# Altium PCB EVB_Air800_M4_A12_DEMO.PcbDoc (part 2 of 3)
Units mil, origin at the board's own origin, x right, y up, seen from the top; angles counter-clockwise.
Board outline 2106 x 2583.39 mil, 2 copper layers (Top, Bottom), stack 12.7 mil thick; 125 components, 94 nets, 414 pads, 454 vias.
Unrouted connection lines stored in the file: 290.
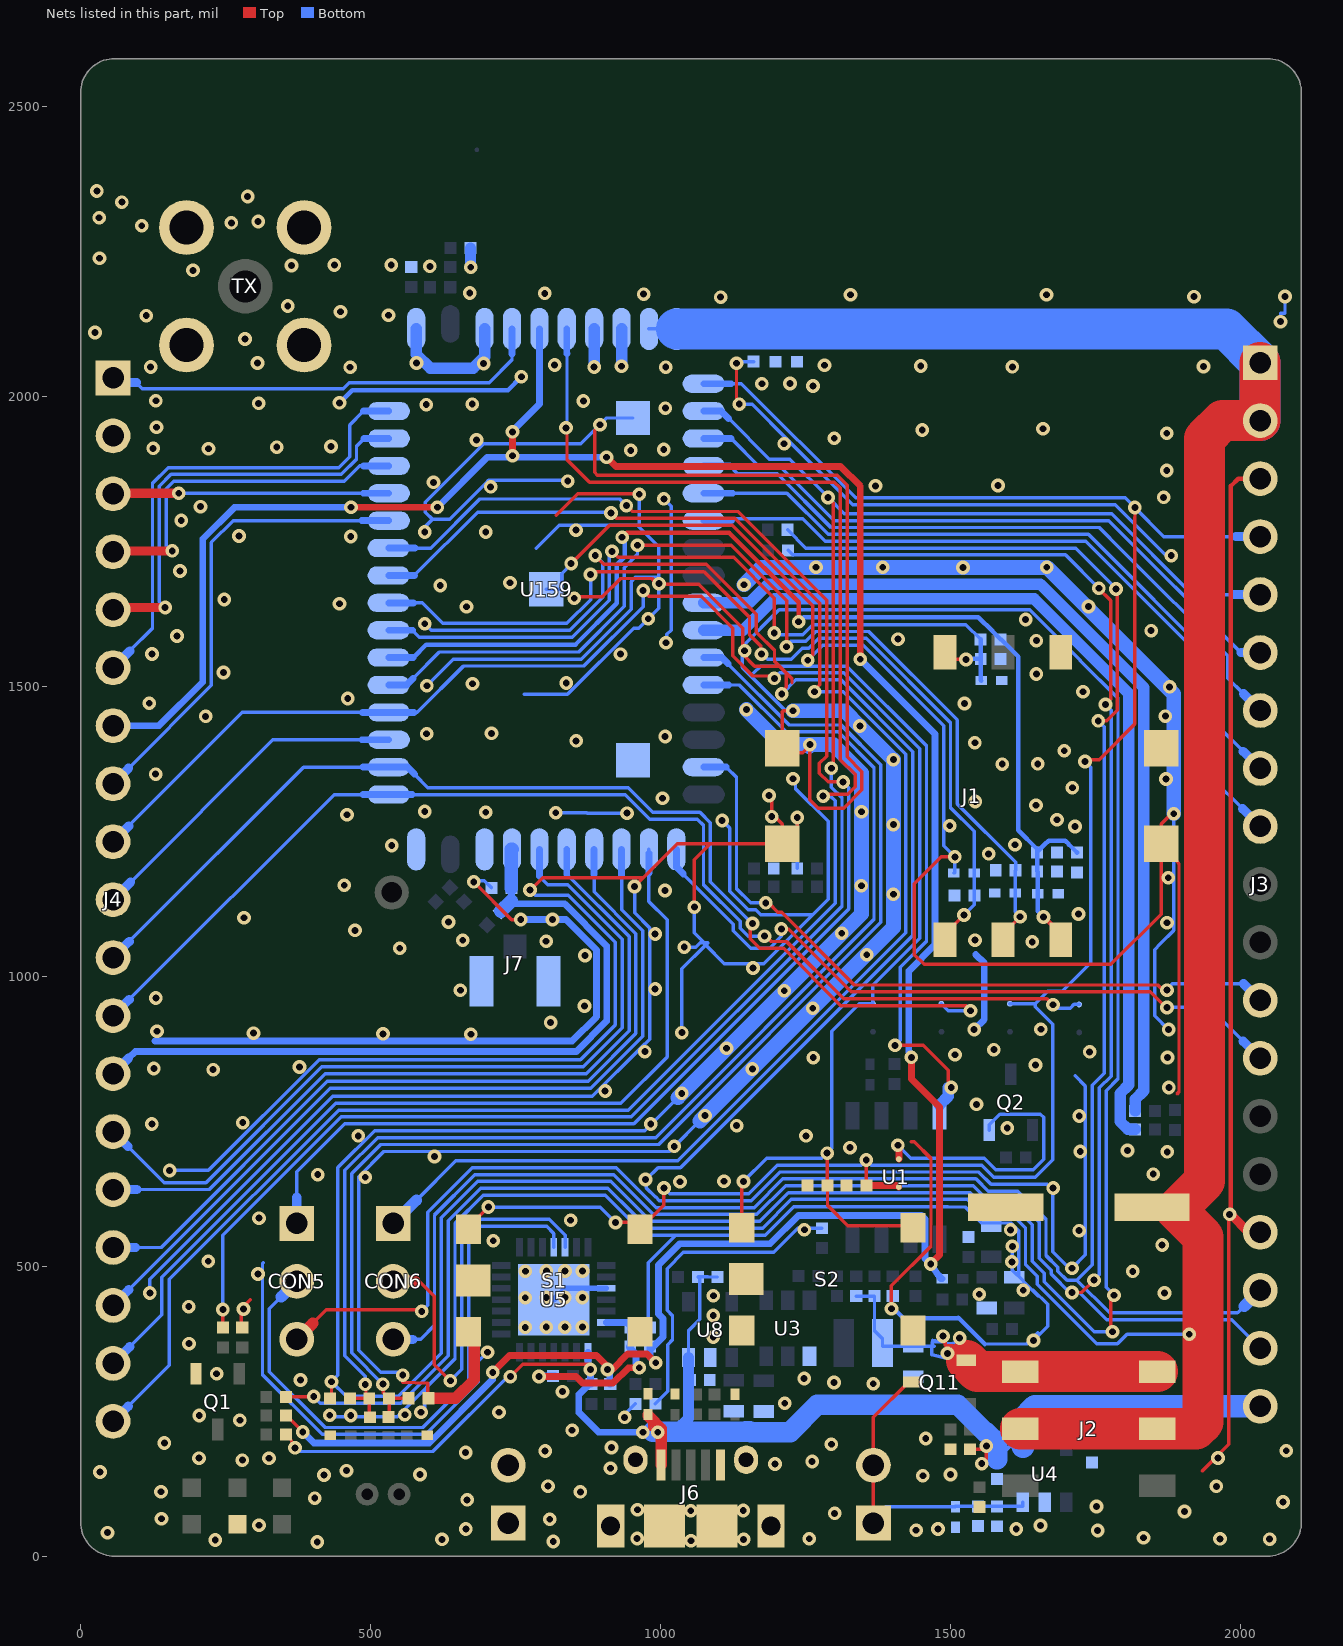
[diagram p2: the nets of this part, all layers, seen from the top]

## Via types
v1: diameter 23.62, hole 11.81, Top to Bottom, 454 vias

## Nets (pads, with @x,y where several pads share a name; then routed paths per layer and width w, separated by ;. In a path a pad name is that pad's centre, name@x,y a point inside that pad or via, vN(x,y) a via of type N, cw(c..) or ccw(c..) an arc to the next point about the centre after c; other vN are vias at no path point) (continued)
GND: C1.2 C2.2 C3.2 C4.1 C5.1 C6.1 C7.2 C8.2 C9.1 C10.1 C11.2 C12.1 C13.2 C14.1 C15.1 C17.1 C18.1 C20.1 C21.2 C22.1 C23.1 C24.1 C25.2 C26.2 C33.1 C34.1 C36.1 C38.2 C45.1 C69.1 C104.1 C105.1 CON4.1 CON4.2 D2.2 J1.3 J1.7 J1.8 J1.9 J1.10 J3.3 J3.16 J4.2 J6.5 J6.6 J6.7 J6.8 J6.9 J6.10 J6.11 J7.1 J7.3 JP4.1 Q1.2 Q2.2 R1.1 R7.1 R8.1 R15.1 R18.1 R26.1 R30.1 R32.2 R43.2 S1.1 S1.2 S1.5 S2.1 S2.2 S2.5 TX.2 TX.3 TX.4 TX.5 U1.8 U3.1 U4.2 U5.3 U5.29 U5.30 U8.2 U159.24 U159.26 U159.42 U159.44 U159.48 U159.49 U159.52 U159.53 U159.54 VR3.2 VR4.2 VR5.2 VR7.2 VR8.2 VR9.2 VR10.2 VR11.2 VR12.2 VR13.2 | length 35132.9
  Top w5.91: R15.1@279.02,394.34 277.05,394.34 277.05,426.43 v1(280.98,426.43) 279.02,428.4 292.8,442.18 ; C105.1@430.6,272.35 432.89,272.35 v1(432.89,300.92) ; v1(555.91,312.29) 555.42,299.93 599.25,298.21 599.25,272.4 C104.1@599.93,272.4 ; v1(678.35,1163.12) 743.34,1098.12 v1(759.36,1098.13) ; v1(775.21,1149.07) 780.32,1152.8 797.44,1169.92 970.38,1169.92 ; 820.28,1795.28 857.81,1832.82 963.85,1832.82 v1(963.85,1831.7) ; v1@846.25,1712.28 912.4,1778.44 1123.9,1778.44 1263.17,1639.17 1263.17,1554.31 v1(1254.27,1545.41) ; v1(851.52,1652.29) 851.52,1654.72 900.24,1654.72 932,1686.49 985.68,1686.49 v1@994.59,1677.58 ; v1(887.9,1726.19) 902.82,1711.26 1079.23,1711.26 1165.75,1624.74 1165.75,1594.08 1197.02,1562.81 1197.02,1543.54 1227.24,1513.32 1227.24,1506.23 ; v1(895.91,1951.54) 886.72,1942.35 886.72,1869.57 891.48,1864.8 1305.01,1864.8 1322.26,1847.56 1322.26,1379.02 1347.85,1353.42 1347.85,1322.08 1316.16,1290.39 1272.35,1290.39 1258.01,1304.73 v1(1258.01,1399.89) 1256.02,1396.14 1245.58,1385.7 1210.59,1385.7 J1.8@1210.59,1393.92 1210.59,1456.6 1212.34,1458.36 v1(1228.8,1458.36) ; v1(955.63,1155.18) 970.38,1169.92 ; v1@997.67,1677.54 v1@997.62,1677.54 ; v1(1058.83,1119.59) 1058.82,1131.85 1058.82,1201.18 1086.21,1228.57 ; v1(1131.51,2057.63) 1131.51,1991.88 v1(1136.1,1987.29) ; v1(1187.6,1312.29) 1192.27,1307.62 v1(1192.27,1275.73) 1197.89,1275.72 1210.59,1263.02 J1.7@1210.59,1228.57 ; v1(1209.51,1487.2) 1217.41,1500.17 1217.41,1522.79 1205.06,1535.13 1162.58,1535.13 1142.04,1555.67 1142.04,1561.8 v1(1145.52,1561.8) 1142.04,1561.9 1142.04,1600.5 1066.03,1676.51 1011.33,1676.51 1000.87,1677.02 998.28,1677.57 997.67,1677.57 v1@994.59,1677.58 ; v1(1236.23,1274.13) 1236.23,1274.88 1236.3,1274.88 1236.3,1254.28 J1.7@1210.59,1228.57 ; v1(1398.69,426.7) 1398.69,466.54 1467.01,534.86 1467.01,685.96 1437.81,715.16 1432.87,715.16 ; v1(1405.02,881.2) 1453.6,881.2 1496.85,837.95 1496.85,818.88 v1(1501.99,808.41) ; v1(1409.78,708.76) v1@1411.57,706.96 ; v1(1508.11,1206.24) 1484.68,1206.27 1438.41,1160 1438.41,1037.37 1455.04,1020.75 1777.22,1020.75 1864.13,1107.66 J1.9@1864.13,1228.57 ; v1(1780.06,387.19) 1775.23,387.43 1777.01,389.22 1777.01,450.12 v1(1782.62,450.12) ; v1(1885.66,1280.72) 1885.24,1280.72 1881.84,1280.72 1864.13,1263.02 J1.9@1864.13,1228.57 ; 1891.26,797.3 1894.82,800.85 1894.82,1194.12 1868.66,1231.72 1865.25,1236.63 1865.25,1228.57 J1.9@1864.13,1228.57 ; 1934.53,146.9 1980.79,193.16 1980.79,588.32 v1(1982.15,589.69) ; 970.38,1169.92 1029.03,1228.57 1086.21,1228.57 ; v1@994.59,1677.58 991.17,1677.59 v1@994.61,1677.56 ; v1@994.61,1677.56 v1@997.62,1677.54 ; v1@994.61,1677.56 996.12,1676.05 v1@997.62,1677.54 ; 1086.21,1228.57 J1.7@1210.59,1228.57
  Top w7.87: v1(1982.15,589.69) 1984.38,591.92 1984.38,1846.1 1997.05,1858.77 J3.3@2034.83,1858.77
  Top w11.81: JP4.1@1411.57,684.97 v1@1411.57,706.96
  Top w15.75: v1(1982.15,589.69) 1983.73,589.69 2014.65,558.77 J3.16@2034.83,558.77
  Top w19.68: C104.1@599.93,272.4 646.97,272.4 679.45,304.88 679.45,377.01 S1.2@669.45,387.01
  Bottom w5.91: v1(119.64,454) 119.64,477.47 435.33,793.16 883,793.16 966.8,876.95 981.67,891.82 981.67,1083.58 955.63,1109.62 v1(955.63,1155.18) ; v1(153.64,665.37) 220.76,665.37 411.43,856.04 862.36,856.04 922.61,916.28 922.61,1059.12 841.63,1140.1 784.17,1140.1 v1(775.21,1149.07) ; 315.38,506.14 313.9,504.66 313.9,313.17 416.98,210.09 595.24,210.09 686.36,301.22 686.36,336.31 v1(701.96,351.91) ; v1(429.86,243.15) 430.32,240.75 546.15,240.75 645.93,340.53 ; v1@555.91,312.28 550.62,317.57 517.64,317.57 479.61,355.6 479.61,654.87 522.83,698.08 1015.68,698.08 1024.28,706.69 1068.35,750.76 ; v1(587.2,248.23) 593.8,247.95 593.8,288.33 645.93,340.46 645.93,340.53 ; v1(593.62,1608.47) 604.88,1597.2 843.61,1597.2 900.44,1654.04 900.44,1713.64 v1(887.9,1726.19) ; v1(593.78,1766.74) 593.78,1775.31 607.05,1788.58 ; v1(597.35,1501.55) 643.17,1547.37 863.44,1547.37 949.72,1633.64 949.72,1681.34 956.79,1688.41 v1@997.23,1688.41 ; v1@672.68,2231.26 676.87,2227.07 v1(673.18,2223.38) ; v1(678.35,1163.12) 680.34,1165.11 696.53,1165.11 708.86,1152.78 C38.2@708.86,1152.59 ; 765.2,1486.67 839.96,1486.67 953.99,1600.69 962.54,1600.69 979.02,1617.17 997.23,1635.38 v1@997.23,1688.41 ; 786.23,1738.68 825.83,1778.28 960.49,1778.28 963.85,1774.93 ; U159.53@803.29,1668.1 829.87,1668.1 829.87,1694.67 v1(846.25,1712.29) ; v1(819.79,1282.45) 873.44,1282.45 874.11,1281.78 v1(942.52,1281.78) ; v1(840.4,1854.35) 839.15,1855.59 703.71,1855.59 699.97,1851.85 636.71,1788.58 607.05,1788.58 ; v1(938.46,239.42) 942.4,239.42 942.4,248.34 956.75,262.69 C25.2@956.95,262.69 ; U159.54@952.9,1963.37 907.75,1963.37 v1(895.91,1951.54) 863.14,1918.77 695.45,1918.77 594.83,1818.15 594.83,1800.8 607.05,1788.58 ; v1(963.85,1831.7) 963.85,1774.93 ; v1(974.53,649.9) v1@975.97,649.9 ; C24.1@982.66,394.64 979.2,398.1 979.2,506.36 1026.56,553.73 ; C7.2@991.45,262.92 991.65,262.92 1012.94,284.21 1012.94,365.08 1021.14,373.28 1021.14,415.05 1011.68,424.52 1011.68,495.89 1039.74,523.95 1195.56,523.95 1237.22,565.6 C45.1@1279.02,565.6 ; v1(997.67,1677.6) 997.67,1688.41 v1@997.23,1688.41 ; v1(1006.19,1823.85) 1018.68,1811.37 1018.68,1597.53 1011.53,1590.38 1011.53,1575.62 v1(1009.97,1575.62) ; v1@1030.39,790.91 973.45,733.97 507.47,733.97 444.03,670.53 444.03,312.06 v1(432.89,300.92) 458.04,275.76 547.75,275.76 622.31,350.32 622.31,583.61 685.17,646.47 914.52,646.47 983.27,577.72 1171.62,577.72 1221.12,627.22 1534.79,627.22 1557.68,604.33 1608.79,604.33 1641.73,571.39 1641.73,508.84 1662.23,488.34 1662.23,473.71 1748.75,387.19 v1(1780.06,387.19) ; v1(1037.27,903.11) 1037.27,1013.46 1078.11,1054.3 ; v1(1041.36,1050.53) 1061.05,1050.53 1069.01,1058.48 1073.93,1058.48 1078.11,1054.3 ; v1@1058.82,1119.59 1058.82,1075.51 1075.85,1058.48 1082.29,1058.48 1078.11,1054.3 ; v1(1106.73,1269.06) 1119.65,1256.14 1119.65,1146.62 1151.38,1114.88 1164.84,1114.88 1173.47,1106.25 1262.68,1106.25 ; v1(1131.51,2057.63) 1134.48,2060.59 C23.1@1161.13,2060.59 ; v1(1136.1,1987.29) 1158.29,1987.29 1220.25,1925.33 1331.84,1813.74 1784.58,1813.74 1872.48,1725.84 v1(1881.45,1725.84) ; 1161.29,1523.64 1173.01,1535.35 1321.51,1535.35 1459.24,1397.63 1459.24,1060.9 1413.87,1015.53 1413.87,890.05 v1(1405.02,881.2) ; v1(1209.51,1487.2) 1234.03,1511.72 1311.74,1511.72 1435.59,1387.87 1435.59,1070.66 1034.88,669.95 996.02,669.95 v1@975.97,649.9 ; v1(1228.79,1340.98) 1233.23,1336.54 1233.23,1323.98 1289.65,1267.56 1289.65,1133.21 1272.56,1116.13 1262.68,1106.25 ; v1(1228.8,1458.36) 1215.95,1458.36 1141.36,1532.94 1141.36,1566.46 v1@1142.04,1565.7 ; v1(1236.23,1274.13) 1235.29,1273.19 1236.3,1272.18 R8.1@1236.3,1186.27 ; v1(1254.27,1545.41) 1280.19,1571.32 1350.1,1571.32 1488.77,1432.66 v1@1488.77,1256.01 ; v1(1409.78,708.76) 1432.06,686.47 1559.06,686.47 1578.74,666.78 1643.25,666.78 1661.24,684.77 1661.24,756.89 1655.54,762.59 1585.94,762.59 1567.23,743.88 Q2.2@1567.23,735.02 ; U1.8@1481.58,759.61 U1.8@1481.58,778.07 ; v1(1499.38,1259.99) 1492.75,1259.99 v1@1488.77,1256.01 ; VR3.2@1506.25,1178.51 1508.11,1178.51 v1(1508.11,1206.24) 1488.77,1225.58 v1@1488.77,1256.01 ; 1559.62,366.05 1631.97,366.05 1651.38,385.46 ; v1(1604.32,562.87) v1@1610.29,568.85 ; v1(1607.34,534.5) 1607.34,493.42 1614.85,485.91 C10.1@1618.11,482.65 ; v1(1643.7,372.05) 1668.07,396.42 1668.07,434.46 1643.44,459.09 1641.67,459.09 ; 1651.38,449.38 1641.67,459.09 ; 1715.76,828.68 1733.4,811.05 1733.4,519.82 v1(1710.15,496.58) 1705.56,496.58 1677.17,524.98 1677.17,631.89 1675.88,633.18 1667.38,641.67 1570.45,641.67 1549.47,662.65 1206.44,662.65 1156.94,613.15 998.44,613.15 991.82,619.77 991.34,619.77 975.97,635.13 v1@975.97,649.9 ; v1(1782.62,450.12) 1769.02,463.72 1769.02,802.81 1789.5,823.29 1789.5,1479.62 1724.42,1544.7 1724.42,1545.26 1637.1,1632.58 1204.83,1632.58 1142.04,1569.79 v1@1142.04,1565.7 ; 1862.39,1056.09 1852.7,1046.4 1852.7,932.41 1876.67,908.45 1878.18,906.94 1878.18,907.28 v1(1876.84,908.63) ; 1862.43,1056.09 1885.66,1079.32 v1(1885.66,1280.72) ; v1(2069.79,2129.57) 2069.79,2143.9 2077.58,2143.9 v1(2077.58,2173) ; 645.93,340.53 645.93,573.83 694.95,622.85 904.74,622.85 939.75,587.83 ; 939.75,587.83 939.75,587.78 940.28,587.26 ; 939.75,587.83 940.28,587.31 940.28,587.26 ; 940.28,587.26 973.81,553.73 1026.56,553.73 ; 963.85,1774.93 997.23,1741.55 v1@997.23,1688.41 ; 1026.56,553.73 1181.03,553.73 1229.92,602.61 1496.06,602.61 1496.31,602.36 1526.24,602.36 1553.8,574.8 1604.33,574.8 v1@1610.29,568.85 ; 1078.11,1054.3 1110.31,1022.1 1178.53,1022.1 1262.68,1106.25 ; v1@1142.04,1565.7 v1(1145.52,1561.8) 1142.04,1561.9 v1@1142.04,1565.7 ; v1@1610.29,568.85 1618.11,561.02 1618.11,507.67 C10.1@1618.11,482.65 ; C10.1@1618.11,482.65 1634.04,466.72 1641.67,459.09
  Bottom w7.87: v1(446.8,1989.42) 468.83,2011.45 737.3,2011.45 v1(760.37,2034.52) ; v1(1398.69,426.7) 1398.69,423.37 1406.6,423.37 1419.58,410.39 1514,410.39 1514,411.67 1559.62,366.05
  Bottom w9.84: U5.29@816.25,442.39 827.67,453.81 835.94,462.08 U5.3@906.81,462.08
  Bottom w11.81: 128.55,888.58 848.05,888.58 889.92,930.45 889.92,1045.61 837.41,1098.13 v1(759.36,1098.13) ; v1(1541.41,908.64) 1558.86,926.09 1558.86,1023.36 1544.11,1038.11
  Bottom w19.68: U159.42@578.88,2116.92 578.88,2073.57 603.11,2049.34 677.43,2049.34 690.39,2062.3 696.99,2068.91 U159.44@696.99,2116.92 ; v1@672.68,2231.26 R26.1@672.68,2256.42 ; v1(885.97,2051.13) U159.48@885.97,2116.92 ; v1(933.22,2052.5) U159.49@933.22,2116.92 ; U1.8@1481.58,778.07 1496.85,793.35 1496.85,808.41 v1(1501.99,808.41)
  Bottom w25.59: v1@1030.39,790.91 1346.96,1107.47 1346.96,1156.48 v1(1346.96,1284.23) 1346.96,1351.23 1298.24,1399.95 v1@1259.47,1399.95 ; 1068.35,750.76 1402.07,1084.48 v1(1402.08,1141.87) v1(1402.08,1261.83) v1(1402.08,1374.06) v1(1344.23,1431.91) 1317.78,1458.36 v1(1228.8,1458.36) ; v1(1144.41,1675.76) 1174.09,1705.43 1220.95,1705.43 1667.36,1705.42 1885.66,1487.12 v1(1885.66,1280.72) ; v1(1148.47,1460.24) 1208.76,1399.95 v1@1259.47,1399.95 ; v1(1258.01,1399.89) 1256.42,1396.9 v1@1259.47,1399.95
  other v1: 408.37,24.42 815.31,25.26 1052.93,26.57 232.49,28.07 623.34,29.06 1143.77,29.1 1256.89,29.98 1965.62,29.89 2051.05,29.38 960.06,30.36 1833.69,31.75 46.37,40.64 1441.4,44.82 1754.45,44.41 664.68,46.9 1479.16,46.79 1614.12,46.79 1655.82,53.03 307.77,53.32 809.28,63.77 139.74,64.69 1300.75,73.83 1904.3,76.96 1052.67,78.44 1143.02,78.95 960.57,80.21 1752.44,85.79 2074.22,93.36 666.85,97.17 404.05,100.12 138.93,111.19 862.14,110.99 806.5,120.83 1959.27,120.43 1453.01,138.74 419.99,140.08 585.55,140.92 1500.52,140.89 33.52,145.29 458.8,147.62 914.02,151.82 1197.77,159.05 1261.97,163.23 279.11,165.7 204.26,169.19 325.04,169.07 1962.16,169.35 664.25,178.76 801.39,181.61 2079.76,182.01 915.83,187.38 1295.1,193.22 144.57,195.19 1457.84,203.15 848.02,217.21 274.76,234.46 204.7,242.73 466.21,242.68 559.41,244.01 721.69,248.19 1214.82,263.92 831.38,283.8 1367.31,297.45 1299.68,299.49 379.36,304.07 1248.11,306.46 234.77,314.7 187.19,366.62 1091.39,378.26 767.06,394.78 803.3,395.1 835.41,395.1 865.61,395.42 1091.39,415.25 186.56,430.46 767.06,445.76 803.3,446.08 835.41,446.08 865.61,446.4 1091.56,449.29 1550.22,451.89 1869.79,454.11 1625.98,458.66 306.09,486.78 767.3,491.46 803.54,491.78 835.65,491.78 865.85,492.1 1814.88,491.31 1606.48,507.67 220.36,508.69 1865.66,536.78 712.01,544.04 1722.45,561.62 1248.53,563.23 845.39,579.59 307.97,583.16 1677.71,635.01 1034.03,645.97 1109.82,646.65 491.02,653.68 409.29,658.2 1850.31,659.02 610.49,689.46 1724.53,697.99 1874.52,697.4 1806.02,699.76 1327.28,704.71 1024.01,706.96 478.96,725.05 1251.4,725.05 1598.38,738.77 1131.71,742.65 123.02,745.52 983.67,745.5 279.72,747.85 1077.14,759.9 1722.76,759.41 1545.43,779.41 1037.09,798.42 904.93,802.51 1877.34,808.6 228.78,839.23 126.52,841.17 1158.88,840.3 377.71,843.89 1647.36,847.25 1263.92,860 1875.06,860.32 1508.49,864.86 1740.66,869.93 973.41,870.35 1575.45,873.81 1114.32,876.11 673.28,900.21 521.82,900.98 298.19,902.24 131.88,905.39 1656.52,908.94 810.91,920.73 1262.93,945.19 869.46,949.11 129.99,962.71 1213.76,975.44 655.17,976.27 991.1,978.3 1160.03,1014.75 870.07,1036.03 1356.14,1037.38 550.74,1048.71 1641.65,1059.66 803.06,1060.78 659.39,1062.59 1543,1062.61 991.1,1073.28 1312.96,1074.52 473.47,1079.49 1874.13,1092.7 634.64,1093.98 813.93,1098.21 281.81,1101.31 1721.51,1107.69 1008.31,1148.39 1346.92,1156.48 454.76,1157.36 1876.11,1170.15 1566.38,1211.49 536.94,1226.04 1612.04,1227.1 1715.42,1258.62 1684.18,1270.33 459.46,1278.96 699.01,1283.24 593.74,1284.59 1647.97,1295.3 1543.21,1301.66 1003.83,1307.46 1710.83,1325.59 1872.45,1340.67 129.55,1348.96 1589.99,1366.28 1651.23,1366.69 1696.93,1389.42 1542.64,1403.19 854.81,1406.41 1008.41,1414.08 596.97,1418.66 708.83,1419.31 215.75,1448.65 1871.31,1449.08 1524.86,1470.77 118.41,1471.37 460.84,1479.38 1729.22,1491.2 1878.66,1499.5 676.12,1505 837.69,1506.31 1648.75,1521.86 246.48,1524.36 123.34,1556.14 931.23,1556.02 1648.75,1579.33 1409.91,1581.89 166.54,1587.31 1846.72,1596.57 1630.23,1615.73 979.19,1617.01 665.66,1637.79 1738.8,1638.09 446.6,1642.78 247.98,1650.28 620.52,1674.42 740.88,1679 171.46,1699.43 1268.48,1705.88 1383.63,1705.91 1522.27,1705.58 1666.58,1705.91 466.09,1758.96 273.46,1759.71 699.02,1766.65 854.69,1769.92 173.65,1786.38 207.01,1810.45 1868.2,1826.39 707.35,1844.48 1371.14,1846.26 1582.68,1846.82 608.81,1852.31 1873.74,1872.9 949.02,1907.45 1005.88,1908.91 125.16,1910.89 220.73,1910.35 338.32,1913.04 432.1,1914.12 1213.68,1918.76 682.94,1925.52 1300.14,1928.27 1873.74,1937.12 1451.84,1942.66 1660.02,1944.88 131.06,1947.4 1008.79,1980.35 596.38,1986.3 675.58,1987.22 307.15,1988.53 129.99,1993.04 867.37,1992.74 1263.6,2018.51 1175.26,2022.42 1223.91,2022.98 120.86,2051.13 464.97,2050.92 1009.52,2051.06 1607.28,2051.49 1449.37,2052.87 1936.86,2052.29 817.74,2054.6 1283.17,2054.25 305.32,2058.04 695.36,2057.34 579.39,2058.29 283.78,2099.68 24.84,2110.74 113.39,2139.82 531.09,2140.66 448.32,2146.52 357.42,2156.67 1104.08,2171.85 1920.57,2172.63 1328.14,2175.97 1666.27,2175.97 971.25,2176.93 671.26,2179.06 800.69,2178.35 193.84,2217.94 602.57,2224.9 363.74,2226.21 535.99,2227.15 437.83,2227.37 32.72,2238.8 105.53,2295.04 260.17,2299.91 306.33,2302.23 32.01,2308.69 71.23,2335.66 288.22,2345.47 28.1,2354.91
GPIO_9: J4.18 U159.18 | length 1583.9
  Bottom w5.91: 84.83,361.25 140.38,416.8 140.38,481.51 440.17,781.3 932.09,781.3 1011.87,861.08 1011.87,1097.93 980.46,1129.34 980.46,1178.61 ; U159.18@980.46,1212.56 U159.18@980.46,1219.28
  Bottom w11.81: 980.46,1178.61 U159.18@980.46,1212.56
  Bottom w15.75: J4.18@56.06,332.48 84.83,361.25
GPIO_13: J3.13 U159.17 | length 1220.1
  Top w5.91: v1(1208.85,1081.75) 1221.34,1081.75 1329.71,973.39 1441.12,973.39 1441.17,973.33 1845.03,973.33 1871.8,946.57 1872.12,946.85 v1(1874.08,946.31)
  Bottom w5.91: 1039.65,1176.47 1125.93,1090.18 1125.93,1078.59 1155.69,1048.83 1188.56,1048.83 1208.85,1069.13 v1(1208.85,1081.75) ; v1(1874.08,946.31) 1872.12,946.57 1947.03,946.57 2005.35,888.24
  Bottom w11.81: U159.17@1027.7,1219.28 1027.7,1188.41 1039.65,1176.47
  Bottom w15.75: 2005.35,888.24 J3.13@2034.83,858.77
GPIO_34: J4.19 U159.47 | length 3210.4
  Top w5.91: v1(837.52,1946.35) 839.08,1946.35 839.08,1891.58 877.89,1852.77 1300.34,1852.77 1310.45,1842.67 1310.45,1374.09 1336.04,1348.5 1336.04,1326.97 1323.28,1314.21 1284.06,1314.21 v1(1280.91,1311.07)
  Bottom w5.91: 82.27,258.69 153.08,329.5 153.08,477.51 445.06,769.49 944.41,769.49 1301.56,1126.64 1301.56,1303.07 1293.57,1311.07 v1(1280.91,1311.07) ; v1(837.52,1946.35) 839.08,1947.91 839.08,2074.42
  Bottom w11.81: U159.47@838.73,2116.92 838.73,2074.59 838.9,2074.42 839.08,2074.42
  Bottom w15.75: J4.19@56.06,232.48 82.27,258.69
GPS_TXD: J3.12 U159.15 | length 1260
  Top w5.91: v1(1182.03,1126.92) 1186.68,1126.92 1202.89,1110.71 1209.5,1110.71 1334.94,985.26 1857.75,985.26 1872.48,970.53 1875.06,973.11 1872.88,975.28 v1(1874.08,976.48)
  Bottom w5.91: 1113.83,1361.01 1131.46,1343.39 1131.46,1151.51 1156.05,1126.92 v1(1182.03,1126.92) ; v1(1874.08,976.48) 1872.83,977.72 1882.89,987.78 2005.81,987.78
  Bottom w11.81: U159.15@1074.95,1361.01 1113.83,1361.01
  Bottom w15.75: 2005.81,987.78 J3.12@2034.83,958.77
HST_RXD: CON6.1 U159.35 | length 2613.4
  Top w5.91: v1(914.86,1799.43) 924.02,1790.28 1128.77,1790.28 1274.98,1644.06 1274.98,1503.02 1264.54,1492.58 v1(1266.08,1491.05)
  Bottom w5.91: 575.89,1691.72 684.83,1800.66 913.63,1800.66 v1(914.86,1799.43) ; 579.48,614.33 647.05,681.9 1030.13,681.9 1423.73,1075.5 1423.73,1383.03 1315.71,1491.05 v1(1266.08,1491.05)
  Bottom w11.81: U159.35@531.64,1691.72 575.89,1691.72
  Bottom w19.68: CON6.1@539.21,574.07 579.48,614.33
HST_TXD: CON5.1 U159.36 | length 2665.5
  Top w5.91: v1(941.57,1812.15) 951.63,1802.09 1133.66,1802.09 1286.8,1648.95 1286.8,1380.01 1274.49,1367.71 1274.49,1350.58 1289.54,1335.54 v1(1315.37,1335.54)
  Bottom w5.91: 372.97,619.2 372.97,663.11 455.65,745.79 954.65,745.79 1325.26,1116.4 1325.26,1325.64 v1(1315.37,1335.54) ; 576.75,1738.96 604.04,1738.96 688.72,1823.64 930.08,1823.64 v1(941.57,1812.15)
  Bottom w11.81: U159.36@531.64,1738.96 576.75,1738.96
  Bottom w15.75: CON5.1@372.97,574.07 372.97,619.2
LCD_CLK/GPIO_16: J4.4 U159.39 | length 617.9
  Top w15.75: J4.4@56.06,1732.48 56.06,1734.11 v1(158.23,1734.11)
  Bottom w5.91: v1(158.23,1734.11) 153.9,1734.11 147.7,1740.3 147.7,1840.95 160.88,1854.13 454.88,1854.13 481.45,1880.7 487.89,1880.7
  Bottom w11.81: 487.89,1880.7 U159.39@531.64,1880.7
LCD_CS/GPIO_15: J4.3 U159.38 | length 476
  Top w15.75: J4.3@56.06,1832.48 57.04,1833.46 v1(169.44,1833.46)
  Bottom w5.91: v1(169.44,1833.46) 488.11,1833.45
  Bottom w11.81: 488.11,1833.45 U159.38@531.64,1833.45
LCD_DATA/GPIO_17: J4.5 U159.40 | length 748.2
  Top w15.75: J4.5@56.06,1632.48 60.05,1636.47 v1(145.96,1636.47)
  Bottom w5.91: v1(145.96,1636.47) 135.89,1646.54 135.89,1845.84 155.99,1865.95 449.99,1865.95 476.05,1892 476.05,1914.84 489.15,1927.94
  Bottom w11.81: 489.15,1927.94 U159.40@531.64,1927.94
LCD_DC/GPIO_18: J4.6 U159.41 | length 837.5
  Bottom w5.91: 85.07,1561.48 124.08,1600.5 124.08,1850.74 151.11,1877.77 445.11,1877.77 464.07,1896.72 464.07,1951.25 488.01,1975.18
  Bottom w11.81: 488.01,1975.18 U159.41@531.64,1975.18
  Bottom w15.75: J4.6@56.06,1532.48 85.07,1561.48
LCD_RST/GPIO_14: J4.8 U159.37 | length 807.9
  Bottom w5.91: 82.99,1359.41 225.74,1502.16 225.74,1748.61 263.33,1786.21 485.18,1786.21
  Bottom w11.81: 485.18,1786.21 U159.37@531.64,1786.21
  Bottom w15.75: J4.8@56.06,1332.48 82.99,1359.41
LDO_VIB: C38.1 J4.13 L6.2 U159.23 | length 1333.7
  Bottom w11.81: 82.99,859.41 94.38,870.8 855.33,870.8 907.64,923.11 907.64,1052.95 835.25,1125.34 743.11,1125.34 743.11,1130.65 C38.1@743.11,1152.59
  Bottom w15.75: J4.13@56.06,832.48 82.99,859.41
  Bottom w23.62: L6.2@725.28,1112.83 743.11,1130.65 ; C38.1@743.11,1152.59 743.11,1219.28 U159.23@744.24,1219.28
MIC+: C103.1 C104.2 L1.1 U159.11 | length 2227.9
  Top w5.91: v1(521.51,296.83) 522.1,296.83 522.1,282.19 C103.1@532.14,272.15 ; L1.1@531.09,239.82 532.14,239.82 C103.1@532.14,272.15 ; C104.2@565.68,272.4 565.43,272.15 C103.1@532.14,272.15
  Bottom w5.91: v1(521.51,296.83) 467.72,350.62 467.72,660.09 517.76,710.13 997.1,710.13 1380.42,1093.45 1380.42,1365.09 1311.77,1433.74 1222.32,1433.74 1116.57,1539.49
  Bottom w11.81: U159.11@1074.95,1549.99 1106.08,1549.99 1116.57,1539.49
MIC-: C103.2 C105.2 L3.1 U159.12 | length 2187.4
  Top w5.91: C105.2@464.86,272.35 C103.2@492.43,272.35 ; v1(491.2,296.44) 492.43,296.44 C103.2@492.43,272.35 ; L3.1@498.98,239.59 497.89,240.68 C103.2@497.89,272.15 ; C103.2@492.43,272.35 492.43,272.15 C103.2@497.89,272.15 ; C103.2@492.43,272.35 497.89,272.35 C103.2@497.89,272.15
  Bottom w5.91: v1(491.2,296.44) 491.2,310.38 455.84,345.73 455.84,665.38 512.62,722.15 992.32,722.15 1368.61,1098.44 1368.61,1360.2 1306.98,1421.82 1217.51,1421.82 1136.59,1502.74 1118.03,1502.74
  Bottom w11.81: U159.12@1074.95,1502.74 1118.03,1502.74
NET_LED/GPIO_28: J3.5 R14.1 U159.2 | length 3271.5
  Top w5.91: R14.1@245.55,394.34 v1(245.55,425.57) ; v1(1289.41,1826.33) 1298.64,1817.1 1298.64,1362.62 v1(1295.16,1359.15)
  Bottom w5.91: v1(245.55,425.57) 245.55,553.27 449.94,757.67 949.7,757.67 1313.43,1121.39 1313.43,1307.91 1294.7,1326.64 1294.7,1359.15 v1(1295.16,1359.15) ; 1117.8,1962.51 1188.12,1892.18 1223.56,1892.18 v1(1289.41,1826.33) 1317.61,1798.13 1778.75,1798.13 1918.11,1658.77 1990.2,1658.77
  Bottom w11.81: U159.2@1074.95,1975.18 1105.12,1975.18 1117.8,1962.51
  Bottom w15.75: 1990.2,1658.77 J3.5@2034.83,1658.77
PWRKEY: C2.1 J3.4 JP3.2 JP4.2 S1.3 S1.4 U159.1 | length 3606.1
  Top w5.91: S1.4@669.45,564.17 669.45,568.1 v1(703.51,602.18) ; v1(922.61,575.54) 922.61,575.86 964.72,575.86 S1.3@964.72,564.17 1006.27,605.72 v1(1006.27,635.01) ; v1(1355.32,683.41) 1355.44,683.28 C2.1@1355.44,639.23 ; v1(1732.57,1370.78) 1742.23,1373.69 1756.99,1373.69 1818.73,1435.42 1818.73,1787.38 1818.24,1787.88 1818.84,1800 v1(1818.63,1808.96)
  Top w11.81: C2.1@1355.44,639.23 1408.89,639.23 JP4.2@1411.38,636.75
  Bottom w5.91: v1(703.51,602.18) 896.17,602.18 922.5,575.86 v1(922.61,575.54) ; v1(1006.27,635.01) 1016.02,625.25 1133.44,625.25 1133.56,625.37 1152.45,625.37 1201.55,674.46 1346.38,674.46 v1(1355.32,683.41) 1364.1,674.62 1554.2,674.62 1575.28,653.54 1646.98,653.54 1677.22,683.78 1677.22,917.47 1646.65,948.04 1646.65,952.91 ; 1121.86,2022.43 1139.97,2022.43 1336.82,1825.58 1802.01,1825.58 v1(1818.63,1808.96) 1868.82,1758.77 1993.03,1758.77 ; JP3.2@1602.98,952.91 1646.65,952.91 ; v1(1732.57,1370.78) 1742.23,1361.11 1742.23,1023.75 1693.16,974.68 1668.43,974.68 1646.65,952.91
  Bottom w11.81: U159.1@1074.95,2022.43 1121.86,2022.43
  Bottom w15.75: 1993.03,1758.77 J3.4@2034.83,1758.77
RESET: C8.1 J4.9 JP1.2 S2.3 S2.4 U159.30 | length 3015.5
  Top w5.91: v1(970.41,1665.68) 981.09,1655.49 1070.34,1655.49 1124.82,1601.01 1124.82,1553.11 1159.7,1518.23 1192.68,1518.23 v1(1196.74,1514.23) ; S2.4@1140.55,566.34 1140.55,643.37 v1(1143.45,646.27) ; v1(1287.84,695.27) 1287.84,639.8 C8.1@1288.42,639.22 1288.42,605.07 1323.22,570.28 1435.83,570.28 S2.3@1435.83,566.34
  Bottom w5.91: 83.19,1259.61 279.08,1455.5 486.64,1455.5 ; 575.12,1455.5 580.59,1455.5 660.63,1535.54 868.31,1535.54 970.63,1637.86 970.63,1656.71 v1(970.41,1665.68) ; v1(1143.45,646.27) 1183.47,686.29 1278.86,686.29 v1(1287.84,695.27) 1295.79,703.21 1295.79,905.66 1343.04,952.91 JP1.2@1366.76,952.91 1366.76,985.12 1447.4,1065.77 1447.4,1392.76 1316.63,1523.53 1206.04,1523.53 v1(1196.74,1514.23)
  Bottom w11.81: 486.64,1455.5 U159.30@531.64,1455.5 575.12,1455.5
  Bottom w15.75: J4.9@56.06,1232.48 83.19,1259.61
SIM_CLK: C4.2 J1.6 U159.34 VR3.1 | length 1624.5
  Top w5.91: v1(879.77,1693.46) 884.61,1698.31 1075.47,1698.31 1153.86,1619.92 1153.86,1589.24 1173.73,1569.37 1173.73,1556.8 v1(1174.54,1556.06) ; J1.6@1490.91,1063.22 1490.91,1073.06 v1(1523.78,1105.94)
  Bottom w5.91: 574.17,1644.48 589.49,1644.48 624.89,1609.07 838.77,1609.07 879.77,1650.07 v1(879.77,1693.46) ; v1(1174.54,1556.06) 1173.76,1556.83 1174.55,1557.61 1184.99,1547.17 1225.77,1547.17 1244.67,1566.08 1256.07,1566.08 1273.13,1583.14 1354.99,1583.14 1500.58,1437.55 1500.58,1291.29 1541.68,1250.18 VR3.1@1541.68,1178.51 1541.68,1160.51 1541.85,1160.34 C4.2@1541.85,1139.78 1541.85,1124.01 v1(1523.78,1105.94)
  Bottom w11.81: U159.34@531.64,1644.48 574.17,1644.48
SIM_DAT: C9.2 J1.1 R10.1 U159.33 VR7.1 | length 1398.8
  Top w5.91: v1(916.89,1733.26) 927.07,1723.07 1126.38,1723.07 1196.72,1652.73 v1(1196.72,1592.48) ; J1.1@1490.91,1559.28 1490.91,1546.81 v1(1527.43,1546.81)
  Bottom w5.91: 572.48,1597.23 584.34,1585.37 848.48,1585.37 912.25,1649.15 912.25,1728.62 v1(916.89,1733.26) ; v1(1196.72,1592.48) 1199.49,1589.7 1245.82,1589.7 1263.07,1606.96 1527.13,1606.96 1552.59,1581.5 R10.1@1552.59,1581.3 ; v1@1527.35,1540.35 v1(1527.43,1546.81)
  Bottom w7.87: v1(1527.43,1546.81) 1528.51,1547.89 C9.2@1552.59,1547.89 ; R10.1@1552.59,1581.3 C9.2@1552.59,1547.89 ; VR7.1@1553.52,1510.44 1552.8,1511.15 C9.2@1552.8,1547.89 C9.2@1552.59,1547.89
  Bottom w11.81: U159.33@531.64,1597.23 572.48,1597.23
SIM_RST: C5.2 J1.5 U159.31 VR4.1 | length 1760.2
  Top w5.91: v1(960.73,1743.88) 1122.28,1743.88 1217.88,1648.27 v1(1217.88,1568.83) ; J1.5@1590.91,1063.22 1590.91,1073.06 v1(1620.78,1102.93)
  Bottom w5.91: 573.65,1514.15 619.23,1559.73 753.59,1559.73 859.1,1559.72 937.84,1638.47 937.84,1705.14 960.73,1728.02 v1(960.73,1743.88) ; v1(1217.88,1568.83) 1217.88,1570.76 1225,1577.89 1250.92,1577.89 1268.11,1595.08 1359.75,1595.08 1512.39,1442.44 1512.39,1297.44 1612.87,1196.96 C5.2@1612.87,1183.25 1612.33,1182.72 VR4.1@1612.33,1143.93 1612.33,1111.37 v1(1620.78,1102.93)
  Bottom w11.81: U159.31@531.64,1502.74 562.24,1502.74 573.65,1514.15
SIM_VDD: C1.1 C3.1 C6.2 J1.4 R10.2 U159.32 VR5.1 | length 1962.8
  Top w7.87: v1(934.26,1757.62) 942.25,1765.6 1118.64,1765.6 1238.55,1645.7 1238.55,1611.67 v1(1238.66,1611.91) ; v1(1661.07,1102.56) 1661.24,1102.73 1690.91,1073.06 J1.4@1690.91,1063.22
  Bottom w7.87: 573.96,1549.99 596.5,1572.53 853.81,1572.53 925.05,1643.77 925.05,1710.44 938.56,1723.95 938.56,1753.32 v1(934.26,1757.62) ; v1(1238.66,1611.91) 1238.58,1611.67 1238.83,1611.41 1238.99,1611.57 1247.17,1619.75 1548.73,1619.75 1573.25,1595.23 1573.25,1595.09 1586.85,1581.5 R10.2@1586.85,1581.3 1587.65,1581.3 1587.65,1581.9 1617.72,1551.84 1617.72,1252.04 1649.89,1219.86 C3.1@1649.89,1214.31 ; v1(1661.07,1102.56) 1650.77,1112.86 1650.77,1180.81 C1.1@1650.27,1181.32 1649.89,1181.32 C3.1@1649.89,1214.11 C3.1@1649.89,1214.31 ; C6.2@1718.91,1213.79 1718.72,1213.79 1704.96,1227.55 1704.96,1227.89 1698.45,1234.4 1669.84,1234.4 1663.49,1228.04 1663.49,1227.9 C3.1@1649.89,1214.31
  Bottom w11.81: U159.32@531.64,1549.99 573.96,1549.99
SPI1_CLK/GPIO_8: J4.17 U159.19 | length 1443.8
  Bottom w5.91: 83.23,459.65 430.76,807.18 880.32,807.18 969.86,896.71 969.86,1078.69 933.22,1115.33 933.22,1174.49
  Bottom w11.81: 933.22,1174.49 U159.19@933.22,1219.28
  Bottom w15.75: J4.17@56.06,432.48 83.23,459.65
SPI1_CS/GPIO_10: J4.16 U159.20 | length 1402.4
  Bottom w5.91: 94.88,532.48 139.19,532.48 425.7,818.99 875.43,818.99 958.04,901.61 958.04,1073.8 885.97,1145.87 885.97,1175.87
  Bottom w11.81: 885.97,1175.87 U159.20@885.97,1219.28
  Bottom w15.75: J4.16@56.06,532.48 94.88,532.48
SPI1_DI/GPIO_12: J4.14 U159.22 | length 1412.6
  Bottom w5.91: 82.15,706.39 144.21,644.33 216.43,644.33 416.33,844.23 867.26,844.23 934.42,911.39 934.42,1064.02 840.25,1158.19 806.15,1158.19 791.48,1172.86
  Bottom w11.81: 791.48,1172.86 U159.22@791.48,1219.28
  Bottom w15.75: J4.14@56.06,732.48 82.15,706.39
SPI1_DO/GPIO_11: J4.15 U159.21 | length 1361
  Bottom w5.91: 96.93,632.48 221.8,632.48 421.73,832.41 872.15,832.41 946.23,906.5 946.23,1068.91 838.73,1176.41
  Bottom w11.81: 838.73,1176.41 U159.21@838.73,1219.28
  Bottom w15.75: J4.15@56.06,632.48 96.93,632.48
SPK+: L4.2 U159.9 | length 1583.1
  Bottom w19.68: U159.9@1074.95,1644.48 1153.95,1644.48 1186.35,1676.88 1655.54,1676.88 1834,1498.41 1834,802.8 1819.09,787.88 L4.2@1819.09,767.86
SPK-: L5.2 U159.10 | length 1599.3
  Bottom w19.68: U159.10@1074.95,1597.23 1142.9,1597.23 1196.96,1651.29 1644.94,1651.29 1808.23,1487.99 1808.23,813.21 1793.11,798.09 1793.11,749.83 1806.57,736.37 L5.2@1819.09,736.37
UART1_CTS/GPIO_3: J3.8 U159.5 | length 1219.6
  Bottom w5.91: 1124.37,1833.45 1218.6,1833.45 1289.44,1762.61 1299.27,1762.61 ; 1299.28,1762.61 1481.61,1762.61 ; 1481.61,1762.61 1738.71,1762.61 1965.85,1535.46 1965.85,1427.74 2005.29,1388.31
  Bottom w11.81: U159.5@1074.95,1833.45 1124.37,1833.45
  Bottom w15.75: 2005.29,1388.31 J3.8@2034.83,1358.77
UART1_DCD/GPIO_31/WD: J4.11 JP2.2 U159.28 | length 1927.8
  Top w5.91: v1(1159.22,1091.23) v1(1159.22,1091.23) 1155.29,1085.86 1155.29,1064.9 1171.7,1048.49 1212.83,1048.49 1311.61,949.71 1527.52,949.71 1535.24,941.99 v1(1535.24,940.76)
  Bottom w5.91: 84.15,1060.56 384.59,1361.01 487.45,1361.01 ; 576.05,1348.84 599.22,1325.67 944.57,1325.67 986.92,1283.32 1068.55,1283.32 1086.37,1265.49 1086.37,1163.19 1155.29,1094.27 1155.29,1091.29 1159.17,1091.29 v1(1159.22,1091.23) ; JP2.2@1484.87,952.91 1497.02,940.76 v1(1535.24,940.76)
  Bottom w11.81: 487.45,1361.01 U159.28@531.64,1361.01 563.88,1361.01 576.05,1348.84
  Bottom w15.75: J4.11@56.06,1032.48 84.15,1060.56
UART1_DTR/GPIO_29: J4.10 U159.29 | length 589.8
  Bottom w5.91: 86.23,1162.65 331.84,1408.25 485.2,1408.25
  Bottom w11.81: 485.2,1408.25 U159.29@531.64,1408.25
  Bottom w15.75: J4.10@56.06,1132.48 86.23,1162.65
UART1_RI/GPIO_30: J4.12 JP5.1 U159.27 | length 2047.6
  Top w5.91: v1(1179.91,1069.51) 1181.16,1070.75 1191.59,1060.33 1217.69,1060.33 1316.5,961.52 1667.06,961.52 v1(1677.47,951.12)
  Bottom w5.91: 84.07,960.49 437.35,1313.77 487.09,1313.77 ; 572.15,1313.77 939.77,1313.77 982.02,1271.51 1063.65,1271.51 1074.56,1260.6 1074.56,1158.29 1137.97,1094.89 1137.97,1083.26 1151.72,1069.51 v1(1179.91,1069.51) ; v1(1677.47,951.12) 1683.44,945.14 1707.06,945.14 1713.64,951.72 JP5.1@1722.58,951.72
  Bottom w11.81: 487.09,1313.77 U159.27@531.64,1313.77 572.15,1313.77
  Bottom w15.75: J4.12@56.06,932.48 84.07,960.49
UART1_RTS/GPIO_2: J3.9 U159.6 | length 1295.3
  Bottom w5.91: 1122.74,1786.21 1122.74,1789.8 1245.54,1789.8 1284.56,1750.79 1343.4,1750.79 ; 1343.4,1750.79 1733.82,1750.79 1953.22,1531.4 1953.22,1340.38 2004.41,1289.19
  Bottom w11.81: U159.6@1074.95,1786.21 1122.74,1786.21
  Bottom w15.75: 2004.41,1289.19 J3.9@2034.83,1258.77
UART1_RXD/GPIO_0: CON6.3 J3.18 R36.1 | length 3763.4
  Top w5.91: v1(1710.25,454.92) 1726.98,454.92 v1(1748.29,476.22) ; v1(1756.6,1669.51) 1756.17,1669.08 1776.77,1648.48 1776.77,1477.91 v1(1767.94,1469.08)
  Bottom w5.91: CON6.3@539.21,374.07 CON6.3@547.78,374.07 ; 573.12,374.07 586.54,374.07 610.5,398.03 610.5,588.51 680.27,658.28 919.41,658.28 988.17,589.53 1166.73,589.53 1216.23,639.03 1539.68,639.03 1560.72,617.99 1611.84,617.99 1653.54,576.29 1653.54,513.73 1674.04,493.23 1674.04,486.76 1707.15,453.65 1708.98,453.65 v1(1710.25,454.92) 1722.99,454.92 1770.05,407.86 1985.73,407.86 J3.18@2034.83,358.77 ; R36.1@1220.46,1734.92 1228.23,1727.15 1698.95,1727.15 v1(1756.6,1669.51) ; v1(1748.29,476.22) 1757.2,485.14 1757.2,807.7 1777.69,828.19 1777.69,1459.33 v1(1767.94,1469.08)
  Bottom w15.75: CON6.3@547.78,374.07 573.12,374.07
UART1_TXD/GPIO_1: CON5.3 J3.17 R37.1 | length 3932.7
  Top w5.91: 400.45,401.55 424.02,425.12 585.77,425.12 v1(588.57,422.32) ; v1(1755.49,1440.91) 1770.25,1440.91 1788.61,1459.27 1788.61,1664.46 1785.52,1667.55 v1(1786.24,1668.26)
  Top w19.68: CON5.3@372.97,374.07 400.45,401.55
  Bottom w5.91: v1(588.57,422.32) 588.24,422.66 598.69,433.11 598.69,593.4 675.38,670.09 924.31,670.09 993.06,601.34 1161.83,601.34 1211.33,650.84 1544.58,650.84 1565.61,629.8 1616.73,629.8 1665.35,581.18 1665.35,518.62 1685.85,498.12 1685.85,491.65 1701.6,475.91 1718.71,475.91 ; R37.1@1219.62,1770.5 1251.14,1738.98 1716.37,1738.98 1786.66,1668.69 v1(1786.24,1668.26) ; v1(1755.49,1440.91) 1765.88,1430.51 1765.88,833.08 1745.21,812.41 1745.21,502.4 1718.71,475.91 ; 2007.22,431.15 1995.74,419.67 1774.94,419.67 1718.71,475.91
  Bottom w19.68: 2007.22,431.15 J3.17@2034.83,458.77
UART2_CTS/GPIO_7: J3.6 U159.3 | length 1112.8
  Bottom w5.91: 1122.19,1927.94 1170.56,1879.57 1206.72,1879.57 1299.98,1786.3 1773.87,1786.3 2001.4,1558.77
  Bottom w11.81: U159.3@1074.95,1927.94 1122.19,1927.94
  Bottom w15.75: 2001.4,1558.77 J3.6@2034.83,1558.77
UART2_RTS/GPIO_6: J3.7 U159.4 | length 1157.1
  Bottom w5.91: 1119.96,1880.7 1133.23,1867.43 1201.51,1867.43 1294.47,1774.47 1757.36,1774.47 1796.3,1735.54 1978.85,1552.98 1978.85,1514.75 2006.04,1487.56
  Bottom w11.81: U159.4@1074.95,1880.7 1119.96,1880.7
  Bottom w15.75: 2006.04,1487.56 J3.7@2034.83,1458.77
USB_RXD: CON5.2 U5.25 | length 1030.5
  Bottom w5.91: 346.12,447.22 325.71,426.81 325.71,318.06 421.78,221.99 590.2,221.99 669.55,301.35 669.55,560.66 677.98,569.08 803.85,569.08 816.25,556.68 U5.25@816.25,532.94 ; CON5.2@363.96,465.07 CON5.2@372.97,474.07
  Bottom w19.68: 346.12,447.22 CON5.2@363.96,465.07
USB_TXD: CON6.2 U5.26 | length 726.3
  Top w5.91: CON6.2@539.21,474.07 CON6.2@547.14,474.07 ; 576.5,474.07 584.4,474.07 610.16,448.31 610.16,330.46 v1(637.86,302.76)
  Top w19.68: CON6.2@547.14,474.07 576.5,474.07
  Bottom w5.91: v1(637.86,302.76) 657.74,322.64 657.74,565.55 673.11,580.92 808.73,580.92 835.94,553.71 U5.26@835.94,532.94
V_BATTERY: C13.1 C15.2 CON1.1 CON1.2 Q11.3 U4.3 VR8.1 | length 556.7
  Top w5.91: CON1.1@1367.6,57.02 CON1.2@1367.6,157.02 1367.6,239.42 1428.62,300.45 Q11.3@1435.51,300.45
  Bottom w5.91: CON1.1@1367.6,57.02 1367.6,63.57 1389.25,85.22 VR8.1@1508.99,85.22 1508.99,86.04 C15.2@1548.01,86.04 1564.52,86.04 1564.61,85.94 C13.1@1581.12,85.94 1625.47,85.94 U4.3@1625.47,92.77
VBAT: C11.1 C22.2 C23.2 C33.2 J2.1 J2.2 J3.1 J3.2 R4.2 U159.50 U159.51 | length 5712.8
  Top w5.91: R4.2@354.65,274.82 383.2,274.82 v1(402.29,275.31) ; C11.1@1889.4,597.48 1884.74,602.14 C11.1@1848.04,602.14 1878.49,632.59 1913.23,632.59 ; v1(1912.57,382.96) 1936.5,382.95
  Top w70.87: J2.1@1621.2,219.82 1924.35,219.82 1936.5,231.97 1936.5,382.95 1936.5,550.38 1889.4,597.48 1939.11,647.19 1939.11,1928.28 1969.59,1958.77 J3.2@2034.83,1958.77 J3.1@2034.83,2058.77
  Bottom w5.91: v1(402.29,275.31) 413.64,263.95 552.65,263.95 634.12,345.43 634.12,578.72 690.06,634.66 909.63,634.66 952.09,592.2 952.09,592.15 978.41,565.83 1176.43,565.83 1226.01,615.41 1529.9,615.41 1552.79,592.52 1603.9,592.52 1629.92,566.5 1629.92,503.53 1650.42,483.03 1650.42,468.82 1752.73,366.51 1788.66,366.51 1805.1,382.95 v1(1912.57,382.96) ; U159.50@980.46,2116.92 U159.51@1027.7,2116.92 ; C23.2@1161.13,2094.85 1161.13,2116.91 ; C22.2@1198.68,2094.59 1198.86,2094.59 1198.86,2116.92 ; 1235.56,2116.92 1236.14,2116.34 C33.2@1236.14,2094.59
  Bottom w70.87: U159.51@1027.7,2116.92 1161.13,2116.92 1198.86,2116.92 1235.56,2116.92 1976.68,2116.92 J3.1@2034.83,2058.77 J3.2@2034.83,1958.77
VBAT_P: C19.2 C34.2 J2.5 J2.6 L2.2 Q11.2 R29.2 | length 810.4
  Top w5.91: v1(1487.62,379.61) 1489.77,368 1491.81,368 1491.81,363.44 1502.44,363.44 1505.75,360.13 Q11.2@1528.03,337.85
  Top w70.87: Q11.2@1528.03,337.85 1547.63,318.25 J2.5@1621.2,318.25 J2.6@1857.42,318.25
  Bottom w5.91: R29.2@1338.07,448.67 C19.2@1369.57,448.67 1369.57,389.03 1383.35,375.25 L2.2@1383.35,367.38 1383.35,362.45 C34.2@1436.5,362.45 1468.02,362.45 ; v1(1495.48,349.87) 1493.39,341.37 1469.02,347.38 1468.02,347.38 1468.02,362.45 ; v1(1516.37,376.41) 1516.93,367.97 1491.84,366.29 v1@1488.75,369.37 ; 1468.02,362.45 1468.02,362.64 1469.5,372.59 1486.2,370.09 v1@1488.35,369.77 ; 1468.02,362.45 1472.91,362.45 1469.24,362.59 1469.52,370.08 1487.24,369.42 v1@1488.75,369.37 ; v1(1487.62,379.61) 1490.85,369.82 v1@1489.78,370.46 ; v1(1487.62,379.61) v1@1489.55,370.6 ; v1(1487.62,379.61) v1@1489.78,370.46 ; v1@1488.35,369.77 v1@1489.77,369.56 ; v1@1488.35,369.77 1484.58,373.55 v1@1489.55,370.6 ; v1@1488.35,369.77 v1@1488.75,369.37 ; v1@1488.75,369.37 1489.82,369.33 v1@1489.77,369.56 ; v1@1489.55,370.6 v1@1489.78,370.46 ; v1@1489.55,370.6 v1@1489.77,369.56 ; v1@1489.77,369.56 1490,369.53 v1@1489.78,370.46
VBUS: C20.2 C69.2 J3.19 J6.1 R13.2 R28.1 R39.2 R47.2 R50.1 U4.4 U5.8 U8.3 VR11.1 | length 2677.3
  Top w5.91: R13.2@354.65,210.2 361.93,210.2 361.93,202.72 v1(369.98,186.91) ; v1(741.47,309.78) 762.86,331.17 879.41,331.17 v1(879.41,322.1) ; VR11.1@978.86,244.42 981.77,244.42 981.77,239.54 981.77,219.74 v1(995.55,213.83) ; R47.2@1534.26,184.37 1558.61,184.37 v1@1562.48,188.24 ; v1(1554.55,159.71) 1562.48,167.64 v1@1562.48,188.24 ; v1(1562.48,190.21) v1@1562.48,188.24
  Top w19.68: VR11.1@978.86,244.42 978.86,242.45 981.77,239.54 1001.46,219.85 J6.1@1001.46,157.41
  Bottom w5.91: v1(369.98,186.91) 376.32,180.56 607.61,180.56 736.82,309.78 v1(741.47,309.78) ; C69.2@1048.7,304.38 1050.38,304.38 C69.2@1051.18,303.58 ; U8.3@1048.7,342.77 1048.7,389.03 1068.39,408.71 1068.39,478.43 R50.1@1065.02,481.79 1081.64,481.79 1081.89,481.55 R28.1@1098.5,481.55 ; v1(1562.48,190.21) 1562.48,194.15 1563.74,195.41 1580.86,195.41 ; C20.2@1580.86,167.45 1581.05,167.45 1602.83,189.23 U4.4@1625.47,189.23
  Bottom w11.81: U5.8@875.31,351.84 875.31,325.98 v1(879.41,322.1) R39.2@879.41,299.11 ; v1(995.55,213.83) 993.99,214.5 981.77,219.74 975.87,213.83 v1(969.96,213.83) 893.16,213.83 859.4,247.59 859.4,279.2 879.31,299.11 R39.2@879.41,299.11 ; R39.2@879.41,299.11 879.41,296.97 R39.2@881.64,296.97 881.64,299.11 R39.2@879.41,299.11
  Bottom w19.68: v1(995.55,213.83) 995.55,214.5 995.55,219.74 1030.98,219.74 1048.7,237.45 1048.7,304.38 U8.3@1048.7,342.77
  Bottom w35.43: v1(995.55,213.83) 987.01,214.5 993.99,214.5 995.55,214.5 1147.13,214.5 1147.13,215.8 1154.51,215.8 1156.48,213.83 1223.9,213.83 1271.04,260.98 1513.37,260.98 1560.51,213.83 1562.43,213.83 1580.86,195.41 C20.2@1580.86,167.45
  Bottom w39.37: U4.4@1625.47,189.23 1625.47,231.68 1622.22,234.93 1646.05,258.77 J3.19@2034.83,258.77
VDD: C24.2 R35.1 R40.2 U5.6 | length 343.5
  Top w11.81: v1(790.8,309.92) 854.49,309.92 865.93,298.48 898.33,298.48 918.72,298.48 945.23,324.99 v1(963.75,324.99)
  Bottom w11.81: v1(790.8,309.92) 790.68,309.92 790.68,311.11 R35.1@814.91,311.11 R35.1@819.24,311.11 ; U5.6@906.81,403.02 942.29,403.02 948.41,396.9 C24.2@948.41,394.64 948.41,361.79 946.79,361.79 946.79,360.13 958.15,348.77 958.15,329.97 958.42,329.34 v1(963.75,324.99)
VDDIO: D5.2 J4.7 R16.2 R38.1 R40.1 U159.46 | length 4940.4
  Top w5.91: R16.2@354.65,242.48 355.2,242.48 355.2,242.84 383.53,214.51 384.43,213.61 384.25,213.44 v1(383.36,214.34)
  Top w11.81: v1(466.66,1809.26) 602.57,1809.26 v1(615.5,1809.37) ; v1(710.99,317.05) 739.87,345.93 889.62,345.93 911.2,324.36 v1(908.94,322.1) 917.29,322.1 943.8,348.62 977.19,348.62 v1(992.14,333.67) ; v1(745.06,1898.09) 744.9,1899.6 744.9,1938.22 744.41,1938.7 v1(745.17,1939.46) ; v1(907.39,1895.62) 923.33,1879.67 1311.02,1879.67 1345.06,1845.64 v1(1345.06,1547.14) ; v1(1433.16,860.47) 1433.16,823.22 1481.77,774.61 1481.77,519.68 1466.54,504.45 v1(1466.54,503.94)
  Bottom w5.91: v1@743.39,1895.62 743.39,1899.6 744.9,1899.6 v1(745.06,1898.09) ; D5.2@1481.34,482.94 D5.2@1483.6,482.94
  Bottom w11.81: J4.7@56.06,1432.48 135.18,1432.48 210.81,1508.1 210.81,1754.84 265.22,1809.26 v1(466.66,1809.26) ; v1(383.36,214.34) 402.36,195.33 601.5,195.33 710.99,304.82 v1(710.99,317.05) ; v1(615.5,1809.37) 701.75,1895.62 743.39,1895.62 v1(907.39,1895.62) ; v1(745.17,1939.46) 744.29,1940.33 791.48,1987.52 U159.46@791.48,2116.92 ; v1(908.94,322.1) 912.87,322.1 912.87,296.99 R38.1@913.66,296.99 ; v1(992.14,333.67) 982.5,343.3 R40.1@982.5,361.79 985.59,361.79 985.59,358.91 1004.71,378.03 1004.71,409.96 996.91,417.76 996.91,502.01 1033.87,538.96 1189.7,538.96 1238.39,587.65 1450.79,587.65 1456.78,581.66 1456.78,513.69 v1(1466.54,503.94) ; v1(1345.06,1547.14) 1474,1418.19 1474,1054.79 1428.64,1009.42 1428.64,870.49 1435.9,863.22 v1(1433.16,860.47) ; v1@1466.84,503.94 v1(1466.54,503.94) ; D5.2@1481.34,482.94 D5.2@1479.52,484.76 ; D5.2@1486.38,478.48 1483.77,478.48 D5.2@1479.52,484.76 ; v1(1466.54,503.94) D5.2@1478.54,486.21 ; D5.2@1478.54,486.21 1478.54,485.74 D5.2@1479.52,484.76 ; D5.2@1478.54,486.21 D5.2@1479.52,484.76
VRTC: J4.1 U159.45 | length 774.6
  Bottom w5.91: 96.38,2024.29 106.65,2014.02 452.9,2014.02 463.18,2024.29 705.09,2024.29 744.24,2063.44 744.24,2073.64
  Bottom w11.81: 744.24,2073.64 U159.45@744.24,2116.92
  Bottom w15.75: J4.1@56.06,2032.48 56.06,2024.29 96.38,2024.29
pads on no net: J1.2 J6.4 U1.3 U5.1 U5.2 U5.10 U5.11 U5.12 U5.13 U5.14 U5.15 U5.16 U5.17 U5.18 U5.19 U5.20 U5.21 U5.22 U5.23 U5.24 U5.27 U5.28 U159.16

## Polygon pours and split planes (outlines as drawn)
GND on Bottom "Bottom-GND" (solid, remove dead copper, pour order 0): -190.08,2724.58 2265.14,2724.58 2265.14,-125.16 -190.08,-125.16
GND on Top "Top-GND" (solid, remove dead copper, pour order 2): -105.81,2647.98 2188.54,2647.98 2188.54,-56.22 -105.81,-56.22

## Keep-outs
Top:
  region: 1573.53,348.85 1670.98,348.85 1670.98,90.3 1573.53,90.3 1573.53,348.85
  region: 1815.17,346.63 1895.28,346.63 1895.28,94.3 1815.17,94.3 1815.17,346.63
  region: 280.98,296.51 302.64,296.51 302.64,290.6 280.98,290.6 280.98,296.51
  region: 1966.17,1645.81 1988.19,1645.81 1988.19,1635.55 1966.17,1635.55 1966.17,1645.81
Bottom:
  region: 1306.57,576.04 1501.46,576.04 1501.46,513.04 1306.57,513.04 1306.57,576.04
  region: 1312.48,790.6 1509.33,790.6 1509.33,725.64 1312.48,725.64 1312.48,790.6
  region: 1332.17,339.82 1367.4,339.82 1367.4,326.35 1332.17,326.35 1332.17,339.82
  region: 746.59,554.42 882.73,554.42 927.78,509.37 927.78,369.53 887.61,329.36 746.25,329.36 702.8,372.81 702.8,511.39 742.68,551.27 746.59,551.27 746.59,554.42
Keep-Out Layer:
  region: 333.48,626.63 418.79,626.63 418.79,341.19 333.48,341.19 333.48,626.63
  region: 106.02,172.36 4.06,172.36 4.06,2082.69 106.02,2082.69 106.02,172.36
  region: 1316.42,202.02 1417.43,202.02 1417.43,9.29 1316.42,9.29 1316.42,202.02
  region: 1985.71,2110.37 2086.1,2110.37 2086.1,199.16 1985.71,199.16 1985.71,2110.37
  region: 500.81,628.01 581.1,628.01 581.1,340.6 500.81,340.6 500.81,628.01
  region: 686.5,202.02 787.98,202.02 787.98,5.72 686.5,5.72 686.5,202.02
  region: -10.21,2635.03 -10.98,2369.63 446.71,2369.63 446.71,2242.17 686.4,2242.17 686.4,2189.08 2181.27,2189.08 2181.27,2635.03 -10.21,2635.03
  region: 446.17,2295.42 ccw(c387.66,2295.42) 387.66,2353.92 ccw(c387.66,2295.42) 329.16,2295.42 ccw(c387.66,2295.42) 387.66,2236.92 ccw(c387.66,2295.42)
  region: 244.99,2090.7 ccw(c186.48,2090.7) 186.48,2149.2 ccw(c186.48,2090.7) 127.98,2090.7 ccw(c186.48,2090.7) 186.48,2032.19 ccw(c186.48,2090.7)
  region: 349.97,2192.27 ccw(c287.27,2192.27) 287.27,2254.97 ccw(c287.27,2192.27) 224.57,2192.27 ccw(c287.27,2192.27) 287.27,2129.57 ccw(c287.27,2192.27)
  region: 446.17,2090.7 ccw(c387.66,2090.7) 387.66,2149.2 ccw(c387.66,2090.7) 329.16,2090.7 ccw(c387.66,2090.7) 387.66,2032.19 ccw(c387.66,2090.7)
  region: 244.59,2295.03 ccw(c186.09,2295.03) 186.09,2353.53 ccw(c186.09,2295.03) 127.59,2295.03 ccw(c186.09,2295.03) 186.09,2236.52 ccw(c186.09,2295.03)
  region: 580.56,106.47 ccw(c550.26,106.47) 550.26,136.77 ccw(c550.26,106.47) 519.97,106.47 ccw(c550.26,106.47) 550.26,76.17 ccw(c550.26,106.47)
  region: 523.88,107.53 ccw(c493.58,107.53) 493.58,137.83 ccw(c493.58,107.53) 463.29,107.53 ccw(c493.58,107.53) 493.58,77.24 ccw(c493.58,107.53)
  lines w0.39: 0.03,58.99 ccw(c59.08,58.99) 59.08,-0.07 2046.97,-0.07 ccw(c2046.97,58.99) 2106.02,58.99 2106.02,2524.27 ccw(c2046.97,2524.27) 2046.97,2583.32 59.08,2583.32 ccw(c59.08,2524.27) 0.03,2524.27 0.03,58.99

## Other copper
Top:
  region net GND: 167.28,2153.1 208.23,2153.1 208.23,2025.14 167.28,2025.14 167.28,2153.1
  region net VBAT: 1910.28,635.54 1959.33,635.54 1959.33,561.57 1910.28,561.57 1910.28,635.54
  region net GND: 301.34,2324.38 444.06,2324.38 444.06,2277.18 301.34,2277.18 301.34,2324.38
  region net GND: 362.17,2153.1 403.11,2153.1 403.11,2025.14 362.17,2025.14 362.17,2153.1
  region net GND: 172.1,2357.14 213.04,2357.14 213.04,2201.94 172.1,2201.94 172.1,2357.14
  region net GND: 255.66,58.19 286.02,58.19 286.02,19.34 255.66,19.34 255.66,58.19
  region net GND: 126.34,2115.04 245.24,2115.04 245.24,2069.38 126.34,2069.38 126.34,2115.04
  region net GND: 366.1,2363.27 395.24,2363.5 399.84,2362.58 403.75,2359.97 406.36,2356.07 407.28,2351.46 407.05,2351.46 407.05,2219.44 366.1,2219.44 366.1,2363.27
  region net VBAT_P: 1476,398.15 1516.71,398.15 1555.04,359.82 1555.04,311.97 1503.88,311.97 1476,339.86 1476,398.15
  region net GND: 321.22,2117.65 448.03,2117.65 448.03,2072.51 321.22,2072.51 321.22,2117.65
  region net VBUS: 1525,200.47 1568.02,200.47 1572.66,195.83 1572.66,160.3 1560.87,148.5 1530.01,148.5 1520.52,157.99 1520.52,196.93 1523.53,199.93 1525,199.93 1525,200.47
  region net $$$32127: 1509.5,273.44 1547.35,273.44 1550.89,269.89 1550.89,212.41 1545.58,207.1 1490.41,207.1 1486.48,211.02 1486.48,256.86 1502.91,273.29 1509.5,273.29 1509.5,273.44
  region net VBUS: 967.99,255.17 991.61,255.17 1009.33,237.45 1009.33,180.59 1006.46,177.72 991.34,177.72 956.67,212.38 956.67,249.27 963.32,255.91 967.99,255.91 967.99,255.17
  region net GND: 665.22,85.21 805.1,85.21 805.1,29.99 665.22,29.99 665.22,85.21
  region net GND: 111.69,2317.62 256.81,2317.62 256.81,2273.73 111.69,2273.73 111.69,2317.62
  region net GND: 55.31,1961.92 131.64,1961.92 131.64,1903.36 55.31,1903.36 55.31,1961.92
  region net V_BATTERY: 1412.3,312.4 1458.77,312.4 1463.56,307.61 1463.56,247.6 1403.95,187.99 1403.95,24.67 1399.3,20.03 1331.96,20.03 1325.96,26.02 1325.96,230.96 1407.52,312.52 1412.3,312.52 1412.3,312.4
  region net GND: 664.4,185.13 804.28,185.13 804.28,129.91 664.4,129.91 664.4,185.13
Bottom:
  region net VBUS: 1501.97,259.02 1629.96,259.02 1637.26,251.72 1637.26,163.96 1624.04,150.75 1549.11,150.75 1470.31,229.54 1471.5,230.72 1471.5,248.18 1501.97,248.18 1501.97,259.02
  region net GND: 363.66,2150.83 404.61,2150.83 404.61,2022.87 363.66,2022.87 363.66,2150.83
  region net GND: 664.5,85.09 803.45,85.09 803.45,31.94 664.5,31.94 664.5,85.09
  region net VBAT_P: 1375.68,398.29 1511.76,398.29 1530.87,379.19 1530.87,349.41 1514.61,333.15 1375.68,333.15 1375.68,398.29
  region net GND: 168.78,2150.83 209.72,2150.83 209.72,2022.87 168.78,2022.87 168.78,2150.83
  region net GND: 1966.98,588.35 2036,588.35 2036,529.23 1966.98,529.23 1966.98,588.35
  region net GND: 54.66,1962.18 133.16,1962.18 133.16,1904.16 54.66,1904.16 54.66,1962.18
  region net $$$28334: 1111.69,456.22 1133.62,456.22 1133.62,446.96 1193.25,387.32 1193.25,292.76 1109.2,292.76 1109.2,449.09 1111.69,449.09 1111.69,456.22
  region net GND: 111.43,2316.55 274.3,2316.55 274.3,2272.83 111.43,2272.83 111.43,2316.55
  region net GND: 298.49,2321.54 445.55,2321.54 445.55,2275.89 298.49,2275.89 298.49,2321.54
  region net V_BATTERY: 1339.25,101.27 1339.5,101.27 1352.99,114.76 1635.07,114.76 1639.49,110.34 1639.49,73.82 1636.9,71.23 1436.3,71.23 1394.7,29.63 1339.25,29.63 1339.25,101.27
  region net GND: 367.6,2362.43 396.73,2362.66 401.34,2361.74 405.25,2359.13 407.86,2355.23 408.77,2350.62 408.54,2350.62 408.54,2221.77 367.6,2221.77 367.6,2362.43
  region net GND: 663.67,185.01 802.62,185.01 802.62,131.86 663.67,131.86 663.67,185.01
  region net GND: 1964.5,1887.89 2036.09,1887.89 2036.09,1829.13 1964.5,1829.13 1964.5,1887.89
  region net VBUS: 1032.02,362.24 1062.22,362.24 1066.78,357.68 1066.78,247.98 1097.15,217.61 992.36,217.61 992.36,230.34 1021.8,259.78 1021.8,356.77 1027.39,362.36 1032.02,362.36 1032.02,362.24
  region net GND: 322.72,2115.39 450.24,2115.39 450.24,2069.75 322.72,2069.75 322.72,2115.39
  region net VBAT: 980.05,2151.1 1029.02,2151.1 1029.02,2083.25 980.05,2083.25 980.05,2151.1
  region net GND: 127.83,2112.77 246.73,2112.77 246.73,2066.69 127.83,2066.69 127.83,2112.77
  region net GND: 171.84,2353.9 212.78,2353.9 212.78,2212.31 171.84,2212.31 171.84,2353.9

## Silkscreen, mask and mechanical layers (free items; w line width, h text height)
Silkscreen Top:
  lines w5.91: 250.14,437.11 250.14,639.87 585.13,639.87 585.13,437.11 250.14,437.11 ; 331.23,341.82 331.23,544.58 639.78,544.58 639.78,341.82 331.23,341.82
  lines w7.87: 1928.04,456.96 1938.87,467.78 ; 1939.27,402.03 1939.27,467.39 ; 1940.84,467.78 1950.68,457.94
  text "EVB_Air800_M4_A12" at 695.47,2090.71 h78.74
  text "JP4" at 1424.54,712.14 h47.24 r90
  text "HOST_UART" at 309.2,422.77 h39.37 r90
  text "UART1" at 627.52,370.87 h39.37 r90
  text "ON" at 1916.81,328.01 h47.24
  text "RESET" at 1225.25,301.69 h39.37
  text "PWER_KEY" at 701.17,299.71 h39.37
  text "-" at 727.83,227.61 h98.43
  text "+" at 1332.17,227.61 h98.43
  text "Battery supply" at 832.17,72.32 h39.37 r90
  text "Battery supply" at 1294.76,66.41 h39.37 r90
  text "(3.5V~4.2V)" at 1471.61,-4.92 h47.24 r90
